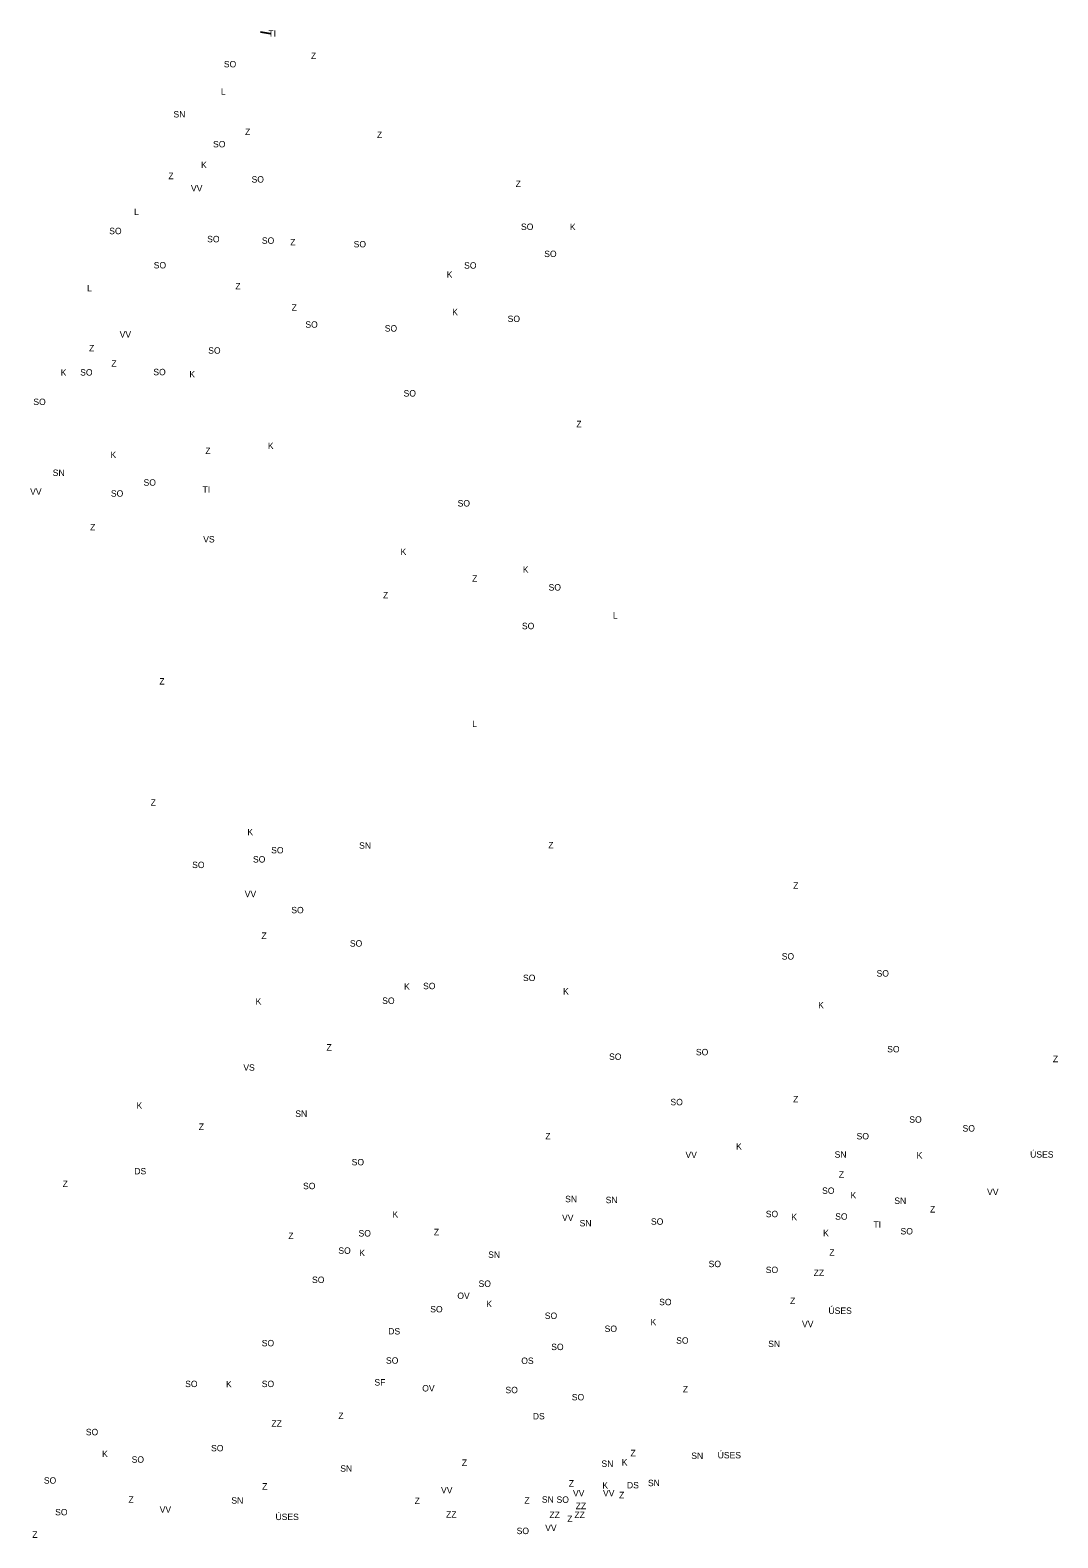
# Model space of a CAD drawing. Extents: x -445021 to -436233, y -1141846 to -1129798.
# Drawn here: x -442146 to -440544, y -1132149 to -1129798 of the extents above; entities that cross this region are included whole.
import ezdxf

# ---------------------------------------------------------------- set-up
doc = ezdxf.new("R2010")
doc.units = 0
doc.layers.add('Vrstva 4', color=7, linetype='Continuous')

msp = doc.modelspace()

# ---------------------------------------------------------------- linework, layer by layer
at = {"layer": 'Vrstva 4'}
msp.add_line((-441771.2, -1129803.7), (-441787, -1129800.8), dxfattribs=at)

# ---------------------------------------------------------------- texts
for s, p in [('TI', (-441774.6, -1129807.8)), ('SO', (-441844, -1129855.8)), ('Z', (-441708.2, -1129842.7)), ('L', (-441848.5, -1129898.6)), ('SN', (-441922.6, -1129933.9)), ('Z', (-441810.9, -1129961.2)), ('Z', (-441605.3, -1129965.9)), ('SO', (-441860.8, -1129980.6)), ('K', (-441879.5, -1130012.9)), ('Z', (-441930.5, -1130030.2)), ('SO', (-441800.8, -1130035.5)), ('Z', (-441389.1, -1130042.4)), ('VV', (-441895.3, -1130049.4)), ('L', (-441984, -1130086)), ('SO', (-442022.7, -1130116)), ('SO', (-441380.7, -1130109.4)), ('K', (-441304.5, -1130109.7)), ('SO', (-441870, -1130128.6)), ('SO', (-441784.7, -1130131)), ('Z', (-441740.5, -1130133.4)), ('SO', (-441641.6, -1130136.6)), ('SO', (-441344.5, -1130151.7)), ('SO', (-441953.3, -1130169.4)), ('K', (-441496.5, -1130184)), ('SO', (-441469.4, -1130169.7)), ('L', (-442057.3, -1130205.1)), ('Z', (-441826.1, -1130202.2)), ('Z', (-441738.4, -1130235.5)), ('K', (-441488, -1130242.4)), ('SO', (-441401.5, -1130253)), ('VV', (-442006.4, -1130277.2)), ('SO', (-441716.9, -1130261.9)), ('SO', (-441593.1, -1130267.9)), ('Z', (-442054.1, -1130298.6)), ('SO', (-441868.4, -1130302.4)), ('Z', (-442019.3, -1130322.5)), ('K', (-442098.3, -1130336.8)), ('SO', (-442068, -1130336.5)), ('SO', (-441953.9, -1130336)), ('K', (-441897.8, -1130339.5)), ('SO', (-441563.8, -1130369.2)), ('SO', (-442141, -1130382.5)), ('Z', (-441294.4, -1130417.1)), ('K', (-442020.7, -1130465.1)), ('Z', (-441872.9, -1130458.8)), ('K', (-441775.3, -1130451.1)), ('SN', (-442110.8, -1130493.1)), ('SO', (-441969.2, -1130508.3)), ('VV', (-442146, -1130522.5)), ('SO', (-442020.1, -1130525.4)), ('TI', (-441877.2, -1130519.2)), ('SO', (-441479.5, -1130540.7)), ('Z', (-442052.4, -1130577.9)), ('VS', (-441876.2, -1130596.8)), ('K', (-441568.4, -1130616.3)), ('Z', (-441456.9, -1130658)), ('K', (-441377.9, -1130644.1)), ('SO', (-441337.7, -1130671.8)), ('Z', (-441595.8, -1130683.9)), ('L', (-441237.4, -1130715.5)), ('SO', (-441379.3, -1130732.1)), ('Z', (-441944.5, -1130818.4)), ('L', (-441456.9, -1130884.5)), ('Z', (-441958.1, -1131007.4)), ('K', (-441807.3, -1131053.5)), ('SO', (-441770.2, -1131081.8)), ('SN', (-441633.1, -1131074.5)), ('Z', (-441338.2, -1131073.9)), ('SO', (-441893.4, -1131104.7)), ('SO', (-441798.6, -1131096)), ('VV', (-441811.4, -1131150.1)), ('Z', (-440956.4, -1131137)), ('SO', (-441738.8, -1131175.2)), ('Z', (-441785.3, -1131215.1)), ('SO', (-441647.5, -1131227.2)), ('SO', (-440974.2, -1131247.4)), ('SO', (-441533.4, -1131293.6)), ('SO', (-441377.6, -1131280.9)), ('SO', (-440826.4, -1131273.9)), ('SO', (-441597.1, -1131316.5)), ('K', (-441563, -1131294.4)), ('K', (-441315.2, -1131301.9)), ('K', (-441794.4, -1131317.6)), ('K', (-440917.4, -1131323.4)), ('Z', (-441683.9, -1131389.3)), ('SO', (-441243.4, -1131403.8)), ('SO', (-441108, -1131396.7)), ('SO', (-440809.8, -1131392.1)), ('Z', (-440551.5, -1131407.4)), ('VS', (-441813.6, -1131420.7)), ('K', (-441980.1, -1131480.1)), ('SO', (-441147.7, -1131474.6)), ('Z', (-440956.4, -1131470)), ('SN', (-441732.6, -1131492.7)), ('SO', (-440775.3, -1131501.9)), ('Z', (-441883, -1131513)), ('Z', (-441342.8, -1131527.8)), ('SO', (-440857.5, -1131527.9)), ('SO', (-440692.3, -1131515.6)), ('K', (-441045.4, -1131543.8)), ('SO', (-441644.7, -1131568.3)), ('VV', (-441124.3, -1131556.9)), ('SN', (-440891.7, -1131556.4)), ('K', (-440763.9, -1131557.7)), ('ÚSES', (-440586.9, -1131556.3)), ('DS', (-441983.6, -1131582.4)), ('Z', (-440885.1, -1131587.4)), ('Z', (-442095.3, -1131602.1)), ('SO', (-441720.5, -1131605.5)), ('SO', (-440911.3, -1131612.8)), ('K', (-440866.9, -1131619.9)), ('VV', (-440654.1, -1131614.8)), ('SN', (-441311.9, -1131625.8)), ('SN', (-441248.7, -1131627.3)), ('SN', (-440798.7, -1131628.5)), ('Z', (-440743.1, -1131641.9)), ('K', (-441581.1, -1131649.8)), ('VV', (-441316.7, -1131655)), ('SN', (-441289.3, -1131663.5)), ('SO', (-441178.1, -1131661)), ('SO', (-440999.1, -1131649.2)), ('K', (-440959.3, -1131653.9)), ('SO', (-440890.9, -1131653.1)), ('TI', (-440831.2, -1131665.4)), ('Z', (-441743.4, -1131683.1)), ('SO', (-441634, -1131679.3)), ('Z', (-441516.5, -1131677.3)), ('K', (-440909.7, -1131678.9)), ('SO', (-440789, -1131676.1)), ('SO', (-441665.5, -1131706.3)), ('K', (-441632.8, -1131709.9)), ('SN', (-441431.9, -1131712.6)), ('Z', (-440900.1, -1131709.3)), ('SO', (-441088.2, -1131727.1)), ('SO', (-440999.1, -1131736.3)), ('SO', (-441706.5, -1131751.8)), ('SO', (-441446.9, -1131757.9)), ('ZZ', (-440924.4, -1131740.8)), ('OV', (-441480, -1131776.7)), ('SO', (-441165.3, -1131786.5)), ('Z', (-440961.2, -1131784.6)), ('SO', (-441522.2, -1131797.7)), ('K', (-441434.8, -1131789.5)), ('SO', (-441343.6, -1131807.9)), ('SO', (-441343.6, -1131807.9)), ('ÚSES', (-440901.4, -1131800)), ('DS', (-441587.7, -1131832.1)), ('SO', (-441250.3, -1131828.2)), ('K', (-441178.7, -1131817.8)), ('VV', (-440942.6, -1131820.8)), ('SO', (-441784.9, -1131850.6)), ('SO', (-441333.6, -1131856.5)), ('SO', (-441138.8, -1131846.5)), ('SN', (-440995.3, -1131851.7)), ('SO', (-441591.2, -1131877.7)), ('OS', (-441380.3, -1131878.1)), ('SO', (-441904.3, -1131914.2)), ('K', (-441840.6, -1131914.6)), ('SO', (-441784.9, -1131914.2)), ('SF', (-441609.2, -1131911.8)), ('OV', (-441534.7, -1131921)), ('SO', (-441404.9, -1131923.7)), ('Z', (-441128.4, -1131922.5)), ('SO', (-441301.5, -1131934.9)), ('Z', (-441665.6, -1131964.2)), ('DS', (-441362.3, -1131964.6)), ('SO', (-442059.2, -1131989.3)), ('ZZ', (-441769.8, -1131975.9)), ('SO', (-441863.9, -1132014.4)), ('Z', (-441209.9, -1132022)), ('K', (-442033.8, -1132023.4)), ('SO', (-441987.7, -1132032.2)), ('SN', (-441662.5, -1132046.2)), ('Z', (-441472.9, -1132037.1)), ('SN', (-441255.3, -1132038.6)), ('K', (-441223.7, -1132036.5)), ('SN', (-441115.2, -1132026.3)), ('ÚSES', (-441074.1, -1132025.4)), ('SO', (-442124.6, -1132064.8)), ('Z', (-441306.1, -1132069.3)), ('SN', (-441182.8, -1132068.7)), ('Z', (-441784.2, -1132074)), ('VV', (-441505.4, -1132079.9)), ('VV', (-441299.7, -1132084.6)), ('VV', (-441252.9, -1132084.6)), ('K', (-441253.9, -1132072.5)), ('Z', (-441227.7, -1132087.5)), ('DS', (-441215.5, -1132072.2)), ('SO', (-442107, -1132114.2)), ('Z', (-441992.7, -1132094.6)), ('VV', (-441944, -1132110.1)), ('SN', (-441832.3, -1132096)), ('Z', (-441546.5, -1132096.4)), ('Z', (-441375.4, -1132095.9)), ('SN', (-441348.2, -1132094.5)), ('SO', (-441325.3, -1132094.7)), ('ZZ', (-441295.5, -1132104.6)), ('ÚSES', (-441763.5, -1132121.6)), ('ZZ', (-441497.5, -1132117.7)), ('VV', (-441343, -1132138.7)), ('ZZ', (-441336.4, -1132118.4)), ('Z', (-441308.6, -1132124.5)), ('ZZ', (-441297.4, -1132118.4)), ('Z', (-442142.7, -1132149.3)), ('SO', (-441387.5, -1132143.5))]:
    msp.add_text(s, height=10, dxfattribs=at).set_placement(p)

doc.saveas('drawing.dxf')
